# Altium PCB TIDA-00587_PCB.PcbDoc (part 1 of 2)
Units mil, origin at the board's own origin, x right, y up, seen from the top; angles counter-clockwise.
Board outline 4500 x 1700 mil, 4 copper layers (Top Layer, MidLayer1, MidLayer2, Bottom Layer), stack 61.6 mil thick; 120 components, 70 nets, 360 pads, 146 vias.
Unrouted connection lines stored in the file: 1.
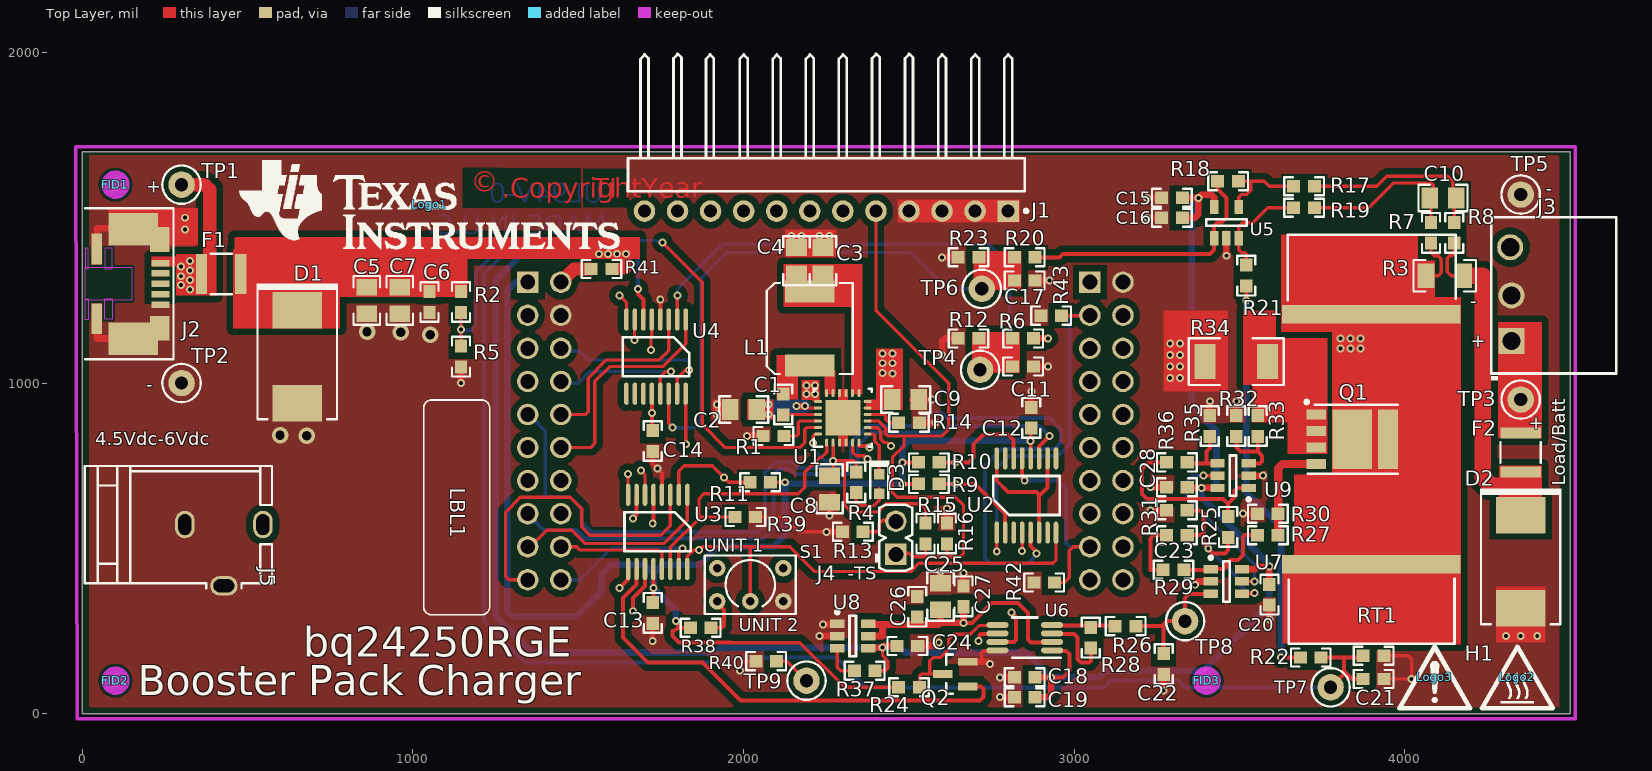
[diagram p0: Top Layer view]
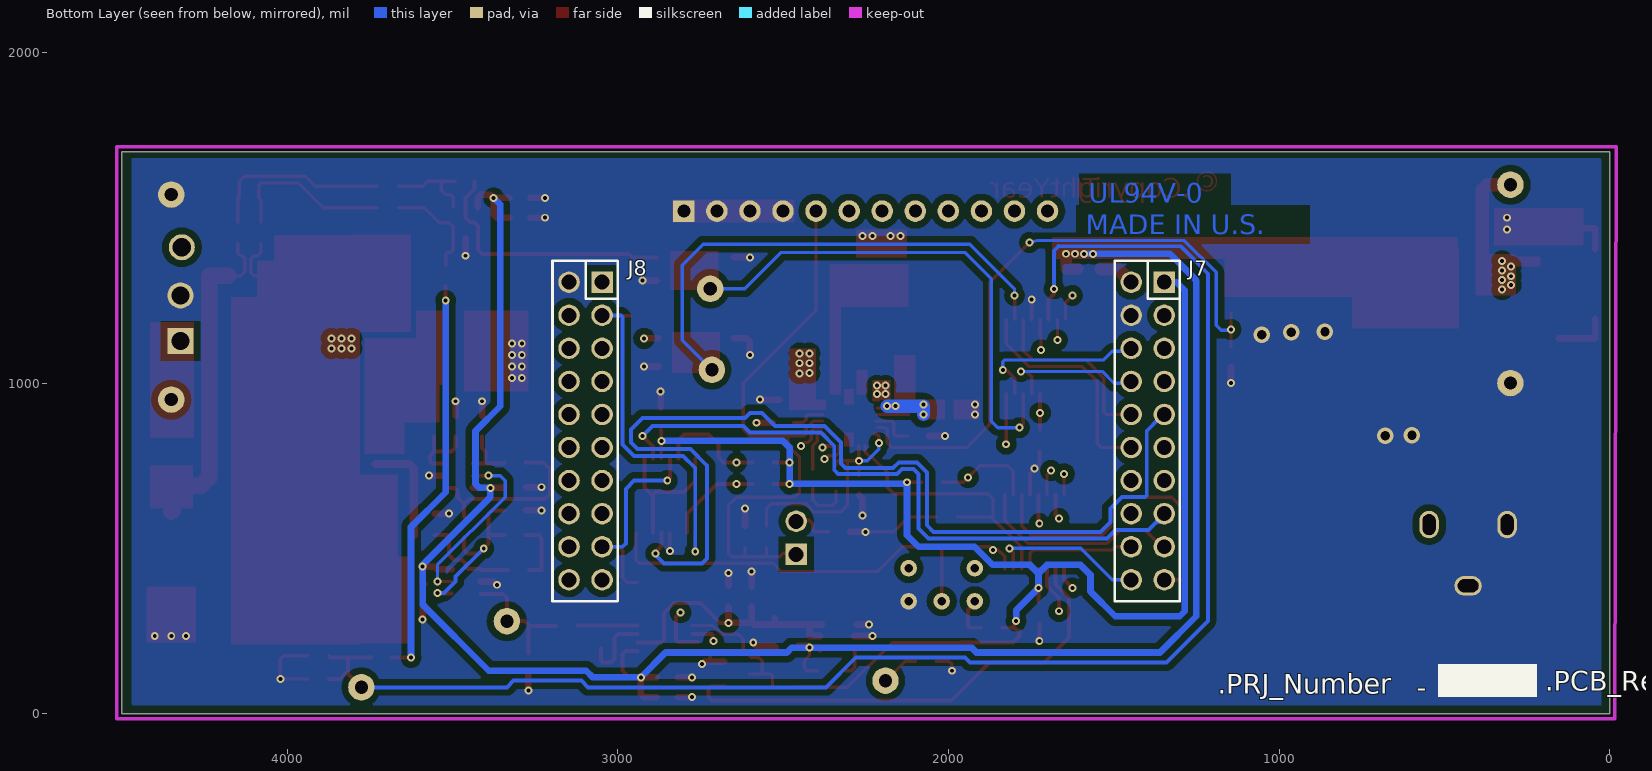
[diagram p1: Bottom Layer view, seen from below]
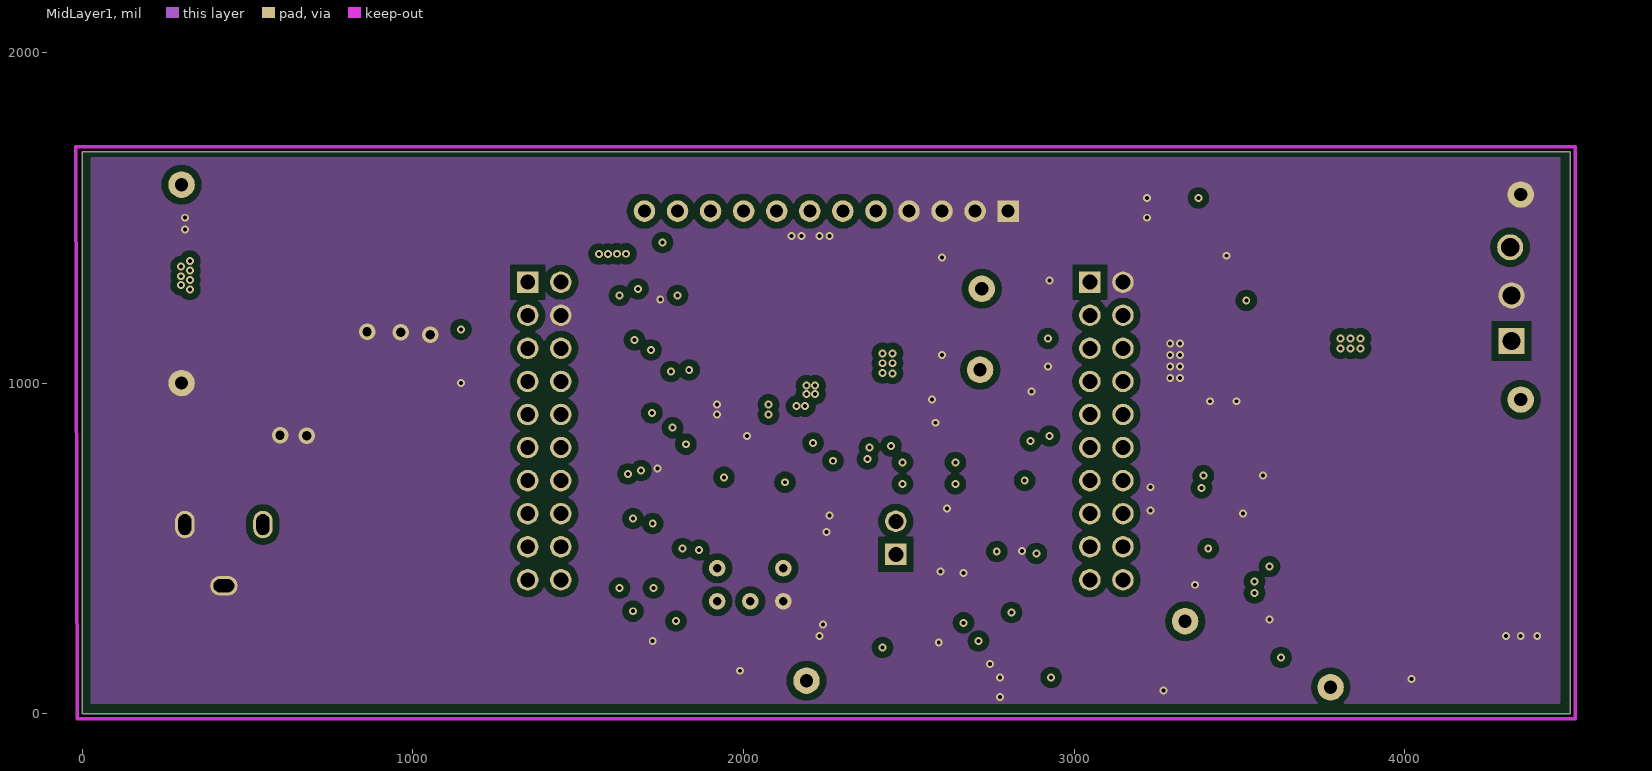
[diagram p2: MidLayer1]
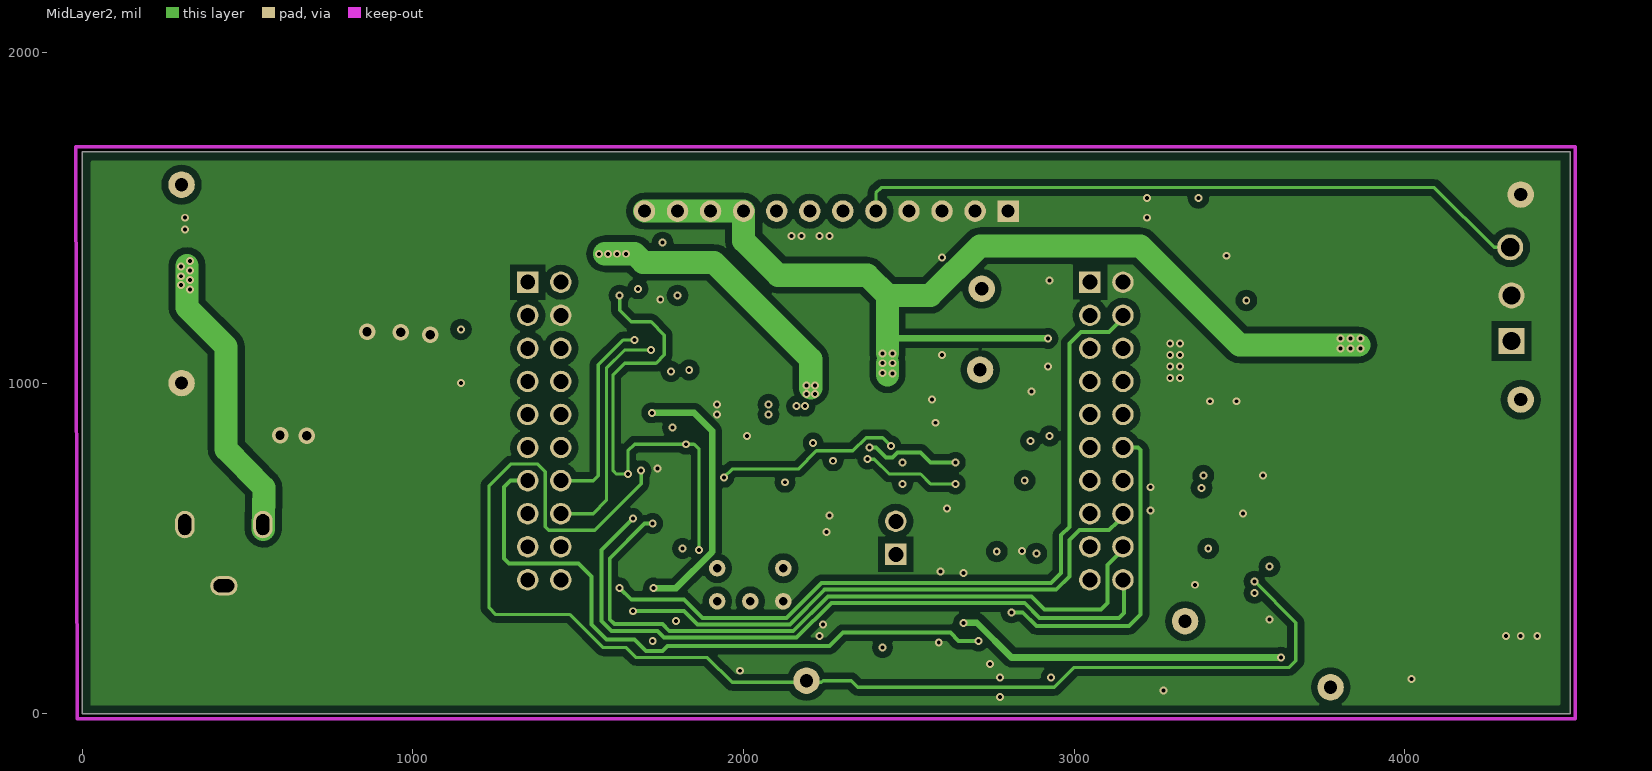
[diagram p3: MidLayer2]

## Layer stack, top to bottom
Top Solder: solder mask 0.4, Solder Resist, Dk 3.5
Top Layer: signal copper 1.4
Dielectric1: prepreg 8, FR-4, Dk 4.8
MidLayer1: signal copper 1.4
Dielectric2: core 40, FR-4, Dk 4.8
MidLayer2: signal copper 1.4
Dielectric3: prepreg 8, FR-4, Dk 4.8
Bottom Layer: signal copper 1.4
Bottom Solder: solder mask 0.4, Solder Resist, Dk 3.5

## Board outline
0,0 0,1700 4500,1700 4500,0 0,0

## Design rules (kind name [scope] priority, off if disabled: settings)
AcuteAngle [All] p1: minimum=4.50000000000000E+0001 checktracksonly=FALSE
AssemblyTestPointUsage [All] p1: valid=2
Clearance Clearance_BoardEdge_MountingHoles [OnCopper and InComponentClass('Mounting Holes') vs IsKeepOut] p1: gap=8
Clearance Clearance_BoardEdge_Poly [OnCopper and InPoly vs IsKeepOut] p2: gap=8
Clearance Clearance_BoardEdge [OnCopper and Not InComponentClass('Logo') and not InComponentClass('FiducialMark') and not InRegion(1000,500,4000,800) and Not IsKeepout vs IsKeepOut] p3: gap=8
Clearance Clearance_Poly [InPolygon] p4: gap=20
Clearance [All] p5: gap=4
ComponentClearance ComponentClearance_Shunt [InComponentClass('Header') vs InComponentClass('Shunt')] p1: gap=0 collisioncheckmode=3 verticalgap=0 showdistances=FALSE
ComponentClearance ComponentClearance_Logo [InComponentClass('Logo')] p2: gap=8 collisioncheckmode=3 verticalgap=8 showdistances=FALSE
ComponentClearance ComponentClearance_ScrewToNut [(HasFootprint('NY PMS 440 0025 PH')) vs (HasFootprint('Keystone_1902C'))] p3: gap=5 collisioncheckmode=3 verticalgap=10 showdistances=FALSE
ComponentClearance ComponentClearance_MountingHoles [InComponentClass('Mounting Holes')] p4: gap=12 collisioncheckmode=3 verticalgap=100000 showdistances=FALSE
ComponentClearance ComponentClearance_SmallPassives [HasFootprint('0201*') or HasFootprint('0402*') or HasFootprint('0508') or HasFootprint('0603*') or HasFootprint('0612') or HasFootprint('0805*') or HasFootprint('0815*') or HasFootprint('0830*') or HasFootprint('1206*') or HasFootprint('1210*') or HasFootprint('1808*') or HasFootprint('1812*') or HasFootprint('1825*') or HasFootprint('2010*') or HasFootprint('2220*') or HasFootprint('2225*') or HasFootprint('2512*') or HasFootprint('2728*') or HasFootprint('3518*') vs HasFootprint('0201*') or HasFootprint('0402*') or HasFootprint('0508') or HasFootprint('0603*') or HasFootprint('0612') or HasFootprint('0805*') or HasFootprint('0815*') or HasFootprint('0830*') or HasFootprint('1206*') or HasFootprint('1210*') or HasFootprint('1808*') or HasFootprint('1812*') or HasFootprint('1825*') or HasFootprint('2010*') or HasFootprint('2220*') or HasFootprint('2225*') or HasFootprint('2512*') or HasFootprint('2728*') or HasFootprint('3518*')] p5: gap=8 collisioncheckmode=3 verticalgap=8 showdistances=FALSE
ComponentClearance ComponentClearance_THtoSMT [IsThruComponent vs IsSMTComponent] p6: gap=8 collisioncheckmode=3 verticalgap=8 showdistances=FALSE
ComponentClearance ComponentClearance_THtoTH [IsThruComponent vs IsThruComponent] p7: gap=8 collisioncheckmode=3 verticalgap=8 showdistances=FALSE
ComponentClearance [All] p8: gap=8 collisioncheckmode=3 verticalgap=8 showdistances=FALSE
DiffPairsRouting [All] p1: maxlimit=100 minlimit=10 mostfreqgap=10 toplayer_minwidth=15 toplayer_maxwidth=15 toplayer_prefwidth=15 midlayer1_minwidth=15 midlayer1_maxwidth=15 midlayer1_prefwidth=15 midlayer2_minwidth=15 midlayer2_maxwidth=15 midlayer2_prefwidth=15 bottomlayer_minwidth=15 bottomlayer_maxwidth=15 bottomlayer_prefwidth=15 maxuncoupledlength=1000
FabricationTestPointUsage TestPointUsage [All] p1: valid=2 allowmultiple=FALSE
FabricationTestpoint Testpoint [All] p1: side=3 testpointundercomponent=TRUE minsize=40 maxsize=100 preferedsize=60 minholesize=0 maxholesize=40 preferedholesize=32 testpointgrid=1 allowsidetop=TRUE allowsidebottom=TRUE usegrid=TRUE gridtolerance=0.01
FanoutControl Fanout_LCC [IsLCC] p1: bgadir=Out bgaviamode=Centered fanoutstyle=Auto fanoutdirection=Alternating viagrid=1 // Fanout_LCC (Default Rule)
FanoutControl Fanout_BGA [IsBGA] p2: bgadir=Out bgaviamode=Centered fanoutstyle=Auto fanoutdirection=Alternating viagrid=1 // Fanout_BGA (Default Rule)
FanoutControl Fanout_Default [All] p4: bgadir=Out bgaviamode=Centered fanoutstyle=Auto fanoutdirection=Alternating viagrid=1 // Fanout_Default (Default Rule)
FanoutControl Fanout_Small [(CompPinCount < 5)] p5: bgadir=Out bgaviamode=Centered fanoutstyle=Auto fanoutdirection=OutThenIn viagrid=1 // Fanout_Small (Default Rule)
Height [All] p1: minheight=0 maxheight=500 prefheight=400
HoleSize [All] p1: absolutevalues=TRUE maxlimit=251 minlimit=3 maxpercent=80.000 minpercent=20.000
MinimumAnnularRing MinimumAnnularRing_ThermalPadVias [IsVia and InAnyComponent] p1: minimumring=3
MinimumAnnularRing [All] p2: minimumring=3
MinimumSolderMaskSliver MinimumSolderMaskSliver_Logo [InComponentClass('Logo') vs InComponentClass('Logo')] p1: minsoldermaskwidth=0.7
MinimumSolderMaskSliver [All] p2: minsoldermaskwidth=3.94
PlaneClearance [All] p1: clearance=10
PlaneConnect [All] p1: planeconnectstyle=Direct reliefexpansion=10 reliefentries=4 reliefconductorwidth=10 reliefairgap=10
PolygonConnect [All] p1: connectstyle=Direct reliefconductorwidth=10 reliefentries=4 polygonreliefangle="90 Angle" airgapwidth=10
RoutingVias ThermalPadVias [IsVia and InAnyComponent] p1: holewidth=7.87 width=19.68 viastyle="Through Hole" minholewidth=7.87 minwidth=19.68 maxholewidth=12.99 maxwidth=23.62
RoutingVias [All] p2: holewidth=16 width=34 viastyle="Through Hole" minholewidth=7.87 minwidth=26 maxholewidth=40 maxwidth=65
SMDToCorner [All] p1: distance=30000
SilkToSilkClearance [All] p1: silktosilkclearance=5
SilkToSolderMaskClearance SilkscreenOverComponentPads [IsPad] p1: minsilkscreentomaskgap=5 clearancetoexposedcopper=TRUE
SolderMaskExpansion [All] p1: expansion=1.97
UnpouredPolygon [All] p1: allowunpoured=FALSE
Width [All] p1: maxlimit=100 minlimit=6 preferedwidth=10 checkconnectedcopper=TRUE
13 further rules are at their usual default settings.

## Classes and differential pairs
component class Logo: Logo1
component class PR2182E3_Hdwr: FID1 FID2 FID3 LBL1 Logo1 Logo2 Logo3 ZZ1 ZZ2 ZZ3 ZZ4 ZZ5 ZZ6
component class FiducialMark: FID1 FID2 FID3
component class AssemblyNote: ZZ1 ZZ2 ZZ3 ZZ4 ZZ5 ZZ6
component class Label: LBL1
component class PR2182E3_Charger: C1 C2 C3 C4 C5 C6 C7 C8 C9 C10 C11 C12 C13 C14 C15 C16 C17 C18 C19 C20 C21 C22 C23 C24 C25 C26 C27 C28 D1 D2 D3 F1 F2 H1 J1 J2 J3 J4 J5 J7 J8 L1 Q1 Q2 R1 R2 R3 R4 R5 R6 R7 R8 R9 R10 R11 R12 R13 R14 R15 R16 R17 R18 R19 R20 R21 R22 R23 R24 R25 R26 R27 R28 R29 R30 R31 R32 R33 R34 R35 R36 R37 R38 R39 R40 R41 R42 R43 RT1 S1 TP1 TP2 TP3 TP4 TP5 TP6 TP7 TP8 TP9 U1 U2 U3 U4 U5 U6 U7 U8 U9
component class Header: J4

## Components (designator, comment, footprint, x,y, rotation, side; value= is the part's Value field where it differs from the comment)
C1 "GRM188R71H333KA61D" 0603 2120,935 r270 top
C2 "GRM21BR71E105KA99L" 0805_HV 2000,920 r0 top
C3 "GRM21BR61A106KE19L" 0805_HV 2240,1370 r90 top
C4 "GRM21BR61A106KE19L" 0805_HV 2160,1370 r90 top
C5 "GRM21BR61A106KE19L" 0805_HV 860,1250 r270 top
C6 "GRM21BR61A106KE19L" 0805_HV 960,1250 r270 top
C7 "C0603C104K3RACTU" 0603 1050,1245 r270 top
C8 "GRM21BR71E105KA99L" 0805_HV 2260,680 r90 top
C9 "GRM21BR71E105KA99L" 0805_HV 2490,950 r180 top
C10 "GRM21BR71E105KA99L" 0805_HV 4115,1560 r180 top
C11 "C0603C101J5GACTU" 0603 2845,1050 r0 top
C12 "C0603C104K3RACTU" 0603 2870,895 r90 top
C13 "C0603C104K3RACTU" 0603 1725,305 r270 top
C14 "C0603C104K3RACTU" 0603 1725,825 r270 top
C15 "C0603C104K3RACTU" 0603 3295,1560 r180 top
C16 "GRM1885C1H101JA01D" 0603 3295,1500 r180 top
C17 "C0603C101J5GACTU" 0603 2850,1310 r0 top
C18 "C0603C104K3RACTU" 0603 2850,110 r180 top
C19 "GRM1885C1H101JA01D" 0603 2850,50 r180 top
C20 "C0603C104K3RACTU" 0603 3590,360 r270 top
C21 "GRM188R71E104KA01D" 0603 3905,105 r0 top
C22 "C0603C101J5GACTU" 0603 3270,150 r270 top
C23 "GRM188R71E104KA01D" 0603 3310,540 r0 top
C24 "C0603C104K3RACTU" 0603 2495,205 r0 top
C25 "GRM21BR71E105KA99L" 0805_HV 2595,355 r270 top
C26 "C0603C104K3RACTU" 0603 2525,323.5 r90 top
C27 "GRM1885C1H101JA01D" 0603 2665,355 r90 top
C28 "C0603C104K3RACTU" 0603 3310,685 r180 top
D1 "1.5SMC6.8A" SMC 650,1080 r270 top
D2 "1.5SMC6.8A" SMC 4350,460 r270 top
D3 "LTST-C190CKT" LED_LTST-C190_Red 2410,695 r90 top
F1 "RF1824-000" FUSE_LR2 420,1330 r0 top
F2 "RF1824-000" FUSE_LR2 4350,790 r90 top
FID1 "Fiducial" Fiducial10-20 100,1600 r0 top
FID2 "Fiducial" Fiducial10-20 100,100 r0 top
FID3 "Fiducial" Fiducial10-20 3400,100 r0 top
H1 "DA-T268-101E" Ohmite_DA-T268-101E 3897.87,830 r90 top
J1 "PBC12SGBN" Sullins_PBC12SGBN 2250,1520 r180 top locked
J2 "UX60SA-MB-5ST" UX60SA-MB-5ST 140,1300 r270 top
J3 "OSTOQ031251" On-Shore_OSTOQ031251 4450,1265 r90 top
J4 "61300211121" WURTH_61300211121 2460,532 r90 top
J5 "PJ-102A" CONN_PJ-102A 428.11,572 r180 top
J7 "SSW-110-24-F-D" CONN_SSW-110-23-F-D 1347,1305 r90 bottom locked
J8 "SSW-110-24-F-D" CONN_SSW-110-23-F-D 3047,1305 r90 bottom
L1 "ELL-6RH1R0M" ELL6RH 2200,1165 r90 top
LBL1 "Size: 0.65\" x 0.20 \"" Label_650x200 1132,624 r270 top
Logo1 "Texas Instruments" TI_Stacked_Overlay_Medium 1050,1540 r0 top
Logo2 "CAUTION HOT SURFACE" IEC_HotSurface_Small 4340,110 r0 top
Logo3 "CAUTION.  READ USER GUIDE BEFORE USE" IEC_Caution_Small 4090,110 r0 top
Q1 "PSMN013-30YLC,115" LFPAK 3840,830 r270 top
Q2 "2N7002-7-F" SOT-23 2640,120 r180 top
R1 "CRCW0603133RFKEA" 0603 2090,840 r0 top
R2 "CRCW06031M00FKEA" 0603 1145,1245 r90 top
R3 "LVK12R010DER" 1206 4120,1324.45 r0 top
R4 "CRCW06031K50FKEA" 0603 2340,700 r270 top
R5 "CRCW0603365KFKEA" 0603 1145,1080 r90 top
R6 "CRCW06031M00FKEA" 0603 2845,1135 r0 top
R7 "CRCW060310R0FKEA" 0603 4078.7,1454.45 r270 top
R8 "CRCW060310R0FKEA" 0603 4148.7,1454.45 r270 top
R9 "CRCW06031K00FKEA" 0603 2560,695 r180 top
R10 "CRCW06031K00FKEA" 0603 2560,760 r180 top
R11 "CRCW060310K0FKEA" 0603 2050,700 r0 top
R12 "CRCW06031M00FKEA" 0603 2680,1135 r0 top
R13 "CRCW060310K0FKEA" 0603 2330,550 r0 top
R14 "CRCW0603124RFKEA" 0603 2500,880 r180 top
R15 "CRCW06034K99FKEA" 0603 2550,545 r90 top
R16 "CRCW06039K76FKEA" 0603 2615,545 r270 top
R17 "CRCW060310K0FKEA" 0603 3695,1595 r0 top
R18 "CRCW06031M00FKEA" 0603 3465,1610 r180 top
R19 "CRCW060310K0FKEA" 0603 3695,1530 r0 top
R20 "CRCW06031M00FKEA" 0603 2850,1380 r0 top
R21 "CRCW06031M00FKEA" 0603 3520,1325 r270 top
R22 "CRCW060310K0FKEA" 0603 3715,170 r180 top
R23 "CRCW06031M00FKEA" 0603 2680,1380 r0 top
R24 "CRCW06031M82FKEA" 0603 2500,80 r0 top
R25 "CRCW06031K00FKEA" 0603 3465,565 r270 top
R26 "CRCW06031K00FKEA" 0603 3155,265 r0 top
R27 "CRCW060310R0FKEA" 0603 3585,540 r0 top
R28 "CRCW060310K0FKEA" 0603 3050,230 r90 top
R29 "CRCW06034K75FKEA" 0603 3300,435 r0 top
R30 "CRCW060310K0FKEA" 0603 3585,605 r0 top
R31 "CRCW06031M00FKEA" 0603 3310,615 r180 top
R32 "CRCW060310K0FKEA" 0603 3490,870 r90 top
R33 "CRCW06031K00FKEA" 0603 3555,870 r90 top
R34 "CSRN2010FKR100" 2010M 3490,1065 r0 top
R35 "CRCW06031K00FKEA" 0603 3410,870 r90 top
R36 "CRCW060310K0FKEA" 0603 3310,760 r0 top
R37 "CRCW06031M00FKEA" 0603 2366,130 r0 top
R38 "CRCW060310K0FKEA" 0603 1870,260 r180 top
R39 "CRCW06031M00FKEA" 0603 2005,595 r180 top
R40 "CRCW06031M00FKEA" 0603 2068.19,159.13 r0 top
R41 "CRCW06030000Z0EA" 0603 1570,1345 r180 top
R42 "CRCW06032M00FKEA" 0603 2909,397 r0 top
R43 "CRCW06032M00FKEA" 0603 2930,1204 r0 top
RT1 "ERT-J1VG103FA" 0603 3905,175 r180 top
S1 "G12AP" SW_G1xAP 2020,390 r0 top
TP1 "5000" Keystone5000 300,1600 r0 top
TP2 "5001" Keystone5001 300,1000 r0 top
TP3 "5000" Keystone5000 4350,950 r0 top
TP4 "5002" Keystone5002 2715,1040 r0 top
TP5 "5001" Keystone5001 4350,1570 r0 top
TP6 "5002" Keystone5002 2720,1285 r0 top
TP7 "5002" Keystone5002 3775,80 r0 top
TP8 "5002" Keystone5002 3335,280 r0 top
TP9 "5002" Keystone5002 2190,100 r0 top
U1 "BQ24250RGER" RGE0024H_NV 2300,895 r90 top
U2 "TS3A44159PWR" PW0016A_N 2855,660 r90 top
U3 "TS3A44159PWR" PW0016A_N 1740,550 r270 top
U4 "TS3A44159PWR" PW0016A_N 1735,1080 r270 top
U5 "OPA333AIDBV" DBV0005A_N 3460,1485 r90 top
U6 "DAC8560IDDGK" DGK0008A_N 2850,230 r180 top
U7 "OPA334AIDBVR" DBV0006A_N 3460,400 r0 top
U8 "REF3225AIDBVR" DBV0006A_N 2330,235 r0 top
U9 "OPA334AIDBVR" DBV0006A_N 3480,720 r180 top
ZZ1 "This Assembly Note is for PCB labels only" AssemblyNoteLabel 327,7572 r0 top
ZZ2 "Mating Plug" AssemblyNote 327,7463.11 r0 top
ZZ3 "Transformer Wall Mnt 5V 2A" AssemblyNote 327,7374.56 r0 top
ZZ4 "CBL USB A-Mini B Con 3' 28/28 AWG" AssemblyNote 327,7286 r0 top
ZZ5 "J7, J8 Must be inserted from the bottom with the pins facing up. DO NOT CUT PINS." AssemblyNote 330,7195 r0 top
ZZ6 "Place a 200mil spot of Locktite Output 315 over RT1 and exposed area on the heatsink (You must use the recommended activator)" AssemblyNote 330,7110 r0 top

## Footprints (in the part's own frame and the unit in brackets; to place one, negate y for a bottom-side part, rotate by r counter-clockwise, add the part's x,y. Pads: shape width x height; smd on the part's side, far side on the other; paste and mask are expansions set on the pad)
0603 [mm] "0603 from SM-752 data"
  rect 1x0.95 smd: 1(-0.8,0) 2(0.8,0)
  silkscreen extent -1.52,-0.69 1.52,0.69, body extent -0.87,-0.47 0.87,0.47, height 0.85
0805_HV [mil] "0805 with 30mil clearance between pads"
  rect 50x63 smd: 1(-40,0) 2(40,0)
  silkscreen extent -74,-40 74,40, body extent -43,-29 43,29, height 43
1206 [mm] "1206 from SM-752 data"
  rect 1.3x1.85 smd: 1(-1.45,0) 2(1.45,0)
  silkscreen extent -2.4,-1.21 2.4,1.21, body extent -1.7,-0.9 1.7,0.9, height 1.35
2010M [mm]
  rect 1.6x2.7 smd: 1(-2.4,0) 2(2.4,0)
  silkscreen extent -3.65,-1.8 3.65,1.8, body extent -2.73,-1.45 2.73,1.45, height 1.66
AssemblyNote [mil] "Assembly Note"
AssemblyNoteLabel [mil] "Assembly Note for PCB Labels"
CONN_PJ-102A [mm] "CUI INC"
  oval 1.5x2.1 hole 1 slot 1.6 at 90 deg: 1(-3,0) 2(3,0)
  oval 2.1x1.5 hole 1 slot 1.6 at 0 deg: 3(0,4.7)
  silkscreen extent -3.7,-4.5 10.7,4.9, body extent -3.7,-4.5 10.7,4.9, height 11.02
CONN_SSW-110-23-F-D [mm] "SAMTEC"
  rect 1.65x1.65 hole 1.15: 1(0,0)
  round 1.65 hole 1.15: 2(0,2.54) 3(-2.54,0) 4(-2.54,2.54) 5(-5.08,0) 6(-5.08,2.54) 7(-7.62,0) 8(-7.62,2.54) 9(-10.16,0) 10(-10.16,2.54) 11(-12.7,0) 12(-12.7,2.54) 13(-15.24,0) 14(-15.24,2.54) 15(-17.78,0) 16(-17.78,2.54) 17(-20.32,0) 18(-20.32,2.54) 19(-22.86,0) 20(-22.86,2.54)
  silkscreen extent -24.51,-1.19 1.65,3.81, body extent -24.43,-1.24 1.57,3.81, height 8.59
DBV0005A_N [mm] "SOT23, 5-Leads, Body 2.9x1.6mm, Pitch 0.95mm, Lead Span 2.8mm, IPC Medium Density"
  rect 1.1x0.65 smd: 1(-1.2,0.95) 2(-1.2,0) 3(-1.2,-0.95) 4(1.2,-0.95) 5(1.2,0.95)
  silkscreen extent -0.25,-1.55 0.25,1.55, body extent -1.42,-1.46 1.42,1.46, height 1.08
DBV0006A_N [mm] "SOT23, 6-Leads, Body 2.9x1.6mm, Pitch 0.95mm, Lead Span 2.8mm, IPC Medium Density"
  rect 1.1x0.65 smd: 1(-1.2,0.95) 2(-1.2,0) 3(-1.2,-0.95) 4(1.2,-0.95) 5(1.2,0) 6(1.2,0.95)
  silkscreen extent -1.32,-1.55 0.25,1.95, body extent -1.42,-1.46 1.42,1.46, height 1.11
DGK0008A_N [mm] "TSOP, 8-Leads, Body 3x3mm, Pitch 0.65mm, IPC Medium Density"
  oval 1.7x0.45 smd: 1(-2.1,0.975) 2(-2.1,0.325) 3(-2.1,-0.325) 4(-2.1,-0.975) 5(2.1,-0.975) 6(2.1,-0.325) 7(2.1,0.325) 8(2.1,0.975)
  silkscreen extent -2.75,-1.55 0.95,1.55, body extent -2.45,-1.5 2.45,1.5, height 0.94
ELL6RH [mm] "Panasonic recommended land pattern"
  rect 1.7x3.8 smd: 1(-2.85,0) 2(2.85,0)
  silkscreen extent -3.5,-3.3 3.5,3.3, body extent -3.45,-3.25 3.45,3.25, height 2.8
Fiducial10-20 [mm]
  round 1 smd paste-0.5 mask+0.5: 1(0,0)
  Top Layer keep-out circle w1.178: c0,0 r0.5
FUSE_LR2 [mm] "TE Connectivity"
  rect 0.85x3.1 smd: 1(-1.5,0) 2(1.5,0)
  silkscreen extent -0.8,-1.55 0.8,1.55, body extent -1.71,-1.4 1.71,1.4, height 1
IEC_Caution_Small [mil]
  silkscreen extent -107,-93 107,92
IEC_HotSurface_Small [mil]
  silkscreen extent -107,-93 107,92
Keystone5000 [mil] "For Keystone 500x miniature loop terminals"
  round 80 hole 40: 1(0,0)
  silkscreen extent -58,-58 58,58, body extent -49,-49 49,49, height 182
Keystone5001 [mil] "For Keystone 500x miniature loop terminals"
  round 80 hole 40: 1(0,0)
  silkscreen extent -58,-58 58,58, body extent -49,-49 49,49, height 182
Keystone5002 [mil] "For Keystone 500x miniature loop terminals"
  round 80 hole 40: 1(0,0)
  silkscreen extent -58,-58 58,58, body extent -49,-49 49,49, height 182
Label_650x200 [mil] "Thermal Transfer Label"
  round 1 on Mech13: 0(0,0)
  silkscreen extent -325,-100 325,100, body extent -326,-101 326,101, height 1
LED_LTST-C190_Red [mm] "Lite-On"
  rect 0.8x0.8 smd: 1(-0.75,0) 2(0.75,0)
  silkscreen extent -1.1,-0.8 1.8,0.8, body extent -0.85,-0.45 0.85,0.45, height 0.9
LFPAK [mm] "Renesas LFPAK recommended land pattern  2008-05-26, page 17 of REJ11K0001_surface.pdf"
  rect 0.76x1.52 smd: 1(-1.905,-2.76) 2(-0.635,-2.76) 3(0.635,-2.76) 4(1.905,-2.76)
  rect 4.57x3.04 smd paste-1.52: 5(0,0)
  rect 4.57x1.52 smd paste-0.76: 6(0,2.76)
  silkscreen extent -2.99,-3.61 2.66,3.52, body extent -2.45,-3.23 2.45,3.2, height 1.18
Ohmite_DA-T268-101E [mm] "Ohmite"
  rect 1.4x13.7 smd: 1(-9.6,0) 2(9.6,0)
  silkscreen extent -15.7,-6.5 15.7,6.4, body extent -15.7,-6.4 15.69,6.32, height 10.16
On-Shore_OSTOQ031251 [mm] "TERM BLOCK 3x1, 3.5mm, TH"
  rect 2x2 hole 1.4: 1(-3.5,3.25)
  round 2 hole 1.4: 2(0,3.25) 3(3.7,3.35)
  silkscreen extent -6.5,-4.8 6,4.8, body extent -5.95,-4.75 5.95,4.75, height 7
PW0016A_N [mm] "TSOP, 16-Leads, Body 5x4.4mm, Pitch 0.65mm, IPC Medium Density"
  oval 1.7x0.35 smd: 1(-2.85,2.275) 2(-2.85,1.625) 3(-2.85,0.975) 4(-2.85,0.325) 5(-2.85,-0.325) 6(-2.85,-0.975) 7(-2.85,-1.625) 8(-2.85,-2.275) 9(2.85,-2.275) 10(2.85,-1.625) 11(2.85,-0.975) 12(2.85,-0.325) 13(2.85,0.325) 14(2.85,0.975) 15(2.85,1.625) 16(2.85,2.275)
  silkscreen extent -1.5,-2.55 1.5,2.55, body extent -3.21,-2.5 3.21,2.5, height 0.98
RGE0024H_NV [mm] "QFN, 24-Leads, Body 4x4mm, Pitch 0.5mm, Thermal Pad 2.7x2.7mm, TI Recommended"
  oval 0.6x0.24 smd: 1(-1.9,1.25) 2(-1.9,0.75) 3(-1.9,0.25) 4(-1.9,-0.25) 5(-1.9,-0.75) 6(-1.9,-1.25) 13(1.9,-1.25) 14(1.9,-0.75) 15(1.9,-0.25) 16(1.9,0.25) 17(1.9,0.75) 18(1.9,1.25)
  oval 0.24x0.6 smd: 7(-1.25,-1.9) 8(-0.75,-1.9) 9(-0.25,-1.9) 10(0.25,-1.9) 11(0.75,-1.9) 12(1.25,-1.9) 19(1.25,1.9) 20(0.75,1.9) 21(0.25,1.9) 22(-0.25,1.9) 23(-0.75,1.9) 24(-1.25,1.9)
  rect 2.7x2.7 smd paste-1.35: 25(0,0)
  silkscreen extent -2.22,-2.22 2.22,2.22, body extent -2.07,-2.07 2.07,2.07, height 1.01
SMC [mil] "Molded Diode, 2-Leads, Body 6.9x5.8mm, IPC Medium Density, based on OnSemi component dimensions and land patterns"
  rect 110x150 smd: 1(-140.49,0) 2(140.49,0)
  silkscreen extent -221,-124 189,123, body extent -156,-116 156,116, height 91
SOT-23 [mm] "SOT23, 3-Leads, Body 2.9x1.3mm, Pitch 0.95mm, Lead Span 2.5mm, IPC Medium Density"
  rect 1.5x0.6 smd: 1(-0.95,0.95) 2(-0.95,-0.95) 3(0.95,0)
  silkscreen extent 0.2,-1.5 0.7,1.5, body extent -1.16,-1.45 1.21,1.45, height 1
Sullins_PBC12SGBN [mm] "Sullins Right Angle Header"
  rect 1.65x1.65 hole 1: 1(-13.97,0)
  round 1.65 hole 1: 2(-11.43,0) 3(-8.89,0) 4(-6.35,0) 5(-3.81,0) 6(-1.27,0) 7(1.27,0) 8(3.81,0) 9(6.35,0) 10(8.89,0) 11(11.43,0) 12(13.97,0)
  silkscreen extent -15.47,-12.09 15.24,0.11, body extent -15.24,-12.14 15.24,0.32, height 3.56
SW_G1xAP [mil] "Switch, NKK G Series"
  round 50 hole 26: 1(-100,50) 3(100,50) 4(-100,-50) 5(0,-50) 6(100,-50)
  silkscreen extent -138,-88 138,89, body extent -138,-88 138,89, height 424
TI_Stacked_Overlay_Medium [mil]
  silkscreen extent -576,-136 576,134
UX60SA-MB-5ST [mm] "Hirose Connectors recommended land pattern"
  rect 0.5x1.4 smd: 1(-1.6,2.45) 2(-0.8,2.45) 3(0,2.45) 4(0.8,2.45) 5(1.6,2.45)
  rect 2.5x3.8 smd paste-1.25: 6(-4.2,0.35) 7(4.2,0.35)
  rect 1.9x1.5 smd paste-0.75: 6(-3.4,2.4) 7(3.4,2.4)
  rect 2.35x0.8 smd: 8(-2.675,-2.45) 9(2.675,-2.45)
  Top Layer keep-out region: -1.143,-1.267 -2.718,-1.267 -2.718,-1.826 -1.143,-1.826
  Top Layer keep-out region: -1.143,-3.096 -2.75,-3.1 -2.75,-3.35 -1.143,-3.35
  Top Layer keep-out region: -1.273,0.25 1.273,0.25 1.273,-1.55 1.273,-3.35 -1.273,-3.35 -1.27,-1.547
  Top Layer keep-out region: 1.143,-3.096 2.75,-3.1 2.75,-3.35 1.143,-3.35
  Top Layer keep-out region: 1.143,-1.242 2.718,-1.242 2.718,-1.826 1.143,-1.826
  silkscreen extent -5.8,-3.35 5.8,3.45, body extent -4.95,-4.2 4.95,2.94, height 4.38
WURTH_61300211121 [mm] "Header, 2.54mm, 2x1, TH"
  rect 1.65x1.65 hole 1.15: 1(-1.27,0)
  round 1.65 hole 1.15: 2(1.27,0)
  silkscreen extent -2.54,-1.27 2.54,1.6, body extent -2.54,-1.27 2.54,1.27, height 8.54

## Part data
C1: "CAP, CERM, 0.033uF, 50V, +/-10%, X7R, 0603"
C2 C8 C9 C10 C25: "CAP, CERM, 1uF, 25V, +/-10%, X7R, 0805"
C3 C4 C5 C6: "CAP, CERM, 10uF, 10V, +/-10%, X5R, 0805"
C7 C12 C13 C14 C15 C18 C20 C21 C23 C24 C26 C28: "CAP, CERM, 0.1uF, 25V, +/-10%, X7R, 0603"
C11 C16 C17 C19 C22 C27: "CAP, CERM, 100pF, 50V, +/-5%, C0G/NP0, 0603"
D1 D2: "Diode, TVS, Uni, 6.8V, 1500W, SMC"
D3: "LED, Red, SMD"
F1 F2: "Fuse, Resettable, 1.9A, 6V, SMD"
FID1 FID2 FID3: "Fiducial mark.  There is nothing to buy or mount."
H1: "Heatsink, TO-268 [D3]SMT"
J1: "Header, 12x1, 100mil, R/A, TH"
J2: "Connector, Receptacle, Mini-USB Type B, R/A, Top Mount SMT"
J3: "Header, 3x1 3.5mm, TH"
J4: "Header, 2.54 mm, 2x1, Gold, TH"
J5: "Connector, DC Jack 2.1X5.5 mm, TH"
J7 J8: library part SSW-110-23-F-D, "Connector, Receptacle, 100mil, 10x2, Gold plated, TH"
L1: "Inductor, Shielded Drum Core, Ferrite, 1uH, 3A, 0.019 ohm, SMD"
LBL1: library part THT-14-423-10, "Thermal Transfer Printable Labels, 0.650\" W x 0.200\" H - 10,000 per roll"
Logo1: library part TI_Logo, "Texas Instrument Corporate Signature"
Logo2: library part IEC_HotSurface, "IEC 61010-1 Hot Surface Warning"
Logo3: library part IEC_Caution, "IEC 61010-1 Caution Warning"
Q1: "MOSFET, N-CH, 30V, 32A, LFPAK"
Q2: "MOSFET, N-CH, 60V, 0.17A, SOT-23"
R1: "RES, 133 ohm, 1%, 0.1W, 0603"
R2 R6 R12 R18 R20 R21 R23 R31 R37 R39 R40: "RES, 1.00Meg ohm, 1%, 0.1W, 0603"
R3: "RES, 0.01 ohm, 0.5%, 0.5W, 1206"
R4: "RES, 1.50k ohm, 1%, 0.1W, 0603"
R5: "RES, 365k ohm, 1%, 0.1W, 0603"
R7 R8 R27: "RES, 10.0 ohm, 1%, 0.1W, 0603"
R9 R10 R25 R26 R33 R35: "RES, 1.00k ohm, 1%, 0.1W, 0603"
R11 R13 R17 R19 R22 R28 R30 R32 R36 R38: "RES, 10.0k ohm, 1%, 0.1W, 0603"
R14: "RES, 124 ohm, 1%, 0.1W, 0603"
R15: "RES, 4.99k ohm, 1%, 0.1W, 0603"
R16: "RES, 9.76k ohm, 1%, 0.1W, 0603"
R24: "RES, 1.82Meg ohm, 1%, 0.1W, 0603"
R29: "RES, 4.75k ohm, 1%, 0.1W, 0603"
R34: "RES, 0.1 ohm, 1%, 1W, 2010"
R41: "RES, 0, 5%, 0.1 W, 0603"
R42 R43: "RES, 2.00Meg ohm, 1%, 0.1W, 0603"
RT1: "Thermistor NTC, 10.0k ohm, 1%, 0603"
S1: "Switch, Toggle, SPDT 1Pos, TH"
TP1 TP3: "Test Point, Miniature, Red, TH"
TP2 TP5: "Test Point, Miniature, Black, TH"
TP4 TP6 TP7 TP8 TP9: "Test Point, Miniature, White, TH"
U1: "2A Single Input I2C, Standalone Switch-Mode Li-Ion Battery Charger with Power-Path Management, RGE0024H"
U2 U3 U4: "0.45 ohm QUAD SPDT ANALOG SWITCH QUAD-CHANNEL 2:1 MULTIPLEXER/DEMULTIPLEXER WITH TWO CONTROLS, PW0016A"
U5: "1.8-V, microPower, CMOS Operational Amplifiers, Zero-Drift Series, DBV0005A"
U6: "16-Bit, Ultra-Low Glitch, Voltage Output Digital-to-Analog Converter with 2.5V, 2ppm/°C Internal Reference, DGK0008A"
U7 U9: "0.05 uV/C Max, Single-Supply CMOS Operational Amplifier, 2.7 to 5.5 V, -40 to 125 degC, 6-pin SOT23 (DBV0006A), Green (RoHS & no Sb/Br)"
U8: "2.5 V, 4 ppm / degC, 100 uA Series (Bandgap) Voltage Reference, -40 to 125 degC, 6-pin SOT-23 (DBV), Green (RoHS & no Sb/Br)"
ZZ1: library part AssemblyNoteLabel
ZZ2: library part AssemblyNote, "This is the mating Plug for Connector J3"
ZZ3 ZZ4 ZZ5 ZZ6: library part AssemblyNote

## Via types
v1: diameter 24, hole 12, Top Layer to Bottom Layer, 141 vias
v2: diameter 50, hole 28, Top Layer to Bottom Layer, 4 vias
v3: diameter 50, hole 28, Top Layer to Bottom Layer, tented bottom, 1 vias

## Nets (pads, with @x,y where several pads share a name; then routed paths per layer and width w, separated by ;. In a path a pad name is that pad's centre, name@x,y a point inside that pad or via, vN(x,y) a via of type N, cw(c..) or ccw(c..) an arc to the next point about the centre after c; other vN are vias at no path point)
3.3VDC: C12.1 C13.1 C14.1 J7.1 R9.2 R10.2 R11.2 R24.1 R38.2 U2.12 U3.12 U4.12 | length 5291.8
  Top Layer w10: 1960,215 2170,215 2305,80 R24.1@2468.5,80 ; U2.12@2867.8,772.2 v1(2867.8,825) 2867.8,856.3 C12.1@2870,858.5
  Top Layer w12: C14.1@1722.2,859.29 v1(1722.2,910) U4.12@1722.2,967.8 ; C13.1@1727.2,338.7 v1(1727.2,380) U3.12@1727.2,437.8 ; v1(1795,280) 1805,260 ; R38.2@1838.5,260 1805,260 ; 1960,215 1805,215 1785,235 1785,250 1805,260 ; R11.2@2081.5,700 v1(2125,700) ; v1(2480,695) R9.2@2528.5,695 ; v1(2480,760) R10.2@2528.5,760
  MidLayer2 w20: v1(1722.2,910) 1850,910 1905,855 1905,489.41 1795.59,380 v1(1727.2,380)
  Bottom Layer w10: v1(2125,700) v1@2130,695
  Bottom Layer w20: J7.1@1330,1300 1325,1305 1310,1305 1285,1280 1285,310 1300,295 1495,295 1570,370 1570,420 1600,450 1701.61,450 1727.2,424.41 ; v1(1795,280) 1795,312.2 v1(1727.2,380) 1727.2,424.41 ; v1(2125,700) 2125,540 2090,505 1920.59,505 1865.59,450 1752.8,450 1727.2,424.41 ; v1@2130,695 v1(2480,695) v1(2480,760) 2480,805 2500,825 v1(2867.8,825)
5VDC: C5.1 C6.1 C7.1 C15.1 C16.1 C18.1 C19.1 C20.1 C24.1 C28.1 D1.1 F1.2 R2.2 R37.2 R41.1 U1.19 U5.5 U6.1 U7.6 U8.4 U9.6 | length 7262.5
  Top Layer w10: v1@2190,965 v1(2190,967) 2190,970 2210.79,949.21 2225.2,949.21 ; R37.2@2396.5,130 2428.16,130 2436.18,138.02 2436.18,158.82 2420,175 v1(2420,200)
  Top Layer w12: v1(2930,110) 2965,110 2985,130 2985,180 2975,190 U6.1@2940.2,190
  Top Layer w20: U8.4@2387,195 2392,200 v1(2420,200) 2425,205 2453.5,205 C24.1@2458.5,200 ; C19.1@2881.5,50 2920,50 2930,60 v1(2930,110) C18.1@2881.5,110 ; C16.1@3326.5,1500 3365,1500 3375,1510 v1(3375,1560) ; C15.1@3326.5,1560 v1(3375,1560) ; C28.1@3343.5,683 v1(3385,683) U9.6@3438,683 ; U5.5@3422.6,1532.24 3422.6,1561.14 3413.74,1570 3385,1570 v1(3375,1560) ; U7.6@3502,437 3547,437 3555,445 v1(3590,445) 3590,396.5 C20.1@3585,391.5
  Top Layer w35: R41.1@1608.22,1346 1644,1346 v1(1644,1391)
  MidLayer2 w10: v1@1616,1390 v1(1617,1391)
  MidLayer2 w70: v1@1580,1391 v1@1626,1391 ; v1(1617,1391) v1(1644,1391) 1670,1391 1696,1365 1910,1365 2203,1072 2203,985.31
  Bottom Layer w20: v1@1590,1391 1330,1391 1250,1310 1250,295 1360,185 1915,185 1930,200 v1(2420,200) 2473.35,200 2488.35,185 2855,185 v1(2930,110) 3075,110 3095,130 3390,130 3590,330 v1(3590,445) 3590,450 3385,655 v1(3385,683) 3418,683 3430,695 3430,855 3355.21,929.79 3355.21,1540.21 v1(3375,1560)
  other v1: 2216,967 2190,992 2216,992 1562,1390 1590,1390
ADC_1: J7.6 U4.15 | length 523
  Top Layer w10: U4.15@1798.98,967.8 1798.98,1013.98 1825,1040 v1(1835.39,1040)
  Bottom Layer w10: J7.6@1450,1080 1466,1096 1504,1096 1530,1070 1830,1070 1835.39,1064.61 v1(1835.39,1040)
ADC_2: J7.8 U4.13 | length 442.7
  Top Layer w10: U4.13@1747.8,967.8 1747.8,1018.74 1764.06,1035 v1(1780,1035)
  Bottom Layer w10: J7.8@1450,980 1469,999 1499,999 1535,1035 v1(1780,1035)
ADC_3: J7.10 U4.3 | length 567.4
  Top Layer w10: J7.10@1450,880 1475,905 1522,905 1530,913 1530,1015 1585,1070 1745,1070 1773.39,1098.39 U4.3@1773.39,1192.2
ADC_4: J7.12 U4.1 | length 697.4
  Top Layer w10: J7.12@1450,780 1475,805 1537,805 1550,818 1550,1005 1595,1050 1755,1050 1824.57,1119.57 U4.1@1824.57,1192.2
ADC_5: J7.14 U4.7 | length 665.3
  Top Layer w10: v1(1670,1130) 1670,1191.18 U4.7@1671.02,1192.2
  MidLayer2 w10: J7.14@1450,680 1475,705 1545,705 1560,720 1560,1055 1635,1130 v1(1670,1130)
ADC_6: J7.16 U4.5 | length 812.8
  Top Layer w10: v1(1720,1100) 1720,1140 1722.2,1142.2 U4.5@1722.2,1192.2
  MidLayer2 w10: J7.16@1450,580 1475,605 1545,605 1585,645 1585,1045 1640,1100 v1(1720,1100)
ADC_CH_IDC: C17.1 R20.1 R23.2 TP6.1 U4.14 | length 1559.6
  Top Layer w10: U4.14@1773.39,967.8 1773.39,876.61 v1(1785,865)
  Bottom Layer w10: v1(1785,865) 1850,865 1870,885 1870,1315 1950,1395 2505,1395 2615,1285 TP6.1@2720,1285
ADC_CH_VDC: C11.1 R6.1 R12.2 TP4.1 U4.2 | length 1534.2
  Top Layer w10: U4.2@1798.98,1192.2 1798.98,1263.98 v1(1800,1265)
  Bottom Layer w10: v1(1800,1265) 1800,1285 1935,1420 2741.46,1420 2805,1356.46 2805,1130 TP4.1@2715,1040
ADC_HS_TEMP: C21.1 R22.1 RT1.2 TP7.1 U4.6 | length 4747.7
  Top Layer w12: v1(1680,1285) 1680,1270 1696.61,1253.39 U4.6@1696.61,1192.2 ; R22.1@3746.5,170 3815,170 ; TP7.1@3775,80 3815,120 3815,130 ; C21.1@3873.5,105 3840,105 3815,130 ; RT1.2@3873.5,175 3868.5,170 3815,170 ; 3815,130 3815,170
  Bottom Layer w12: v1(1680,1285) 1680.06,1400 1666.82,1413.82 1296.5,1413.5 1214.5,1330.5 1215,280 1340,155 1935,155 1950,170 2280,170 2370,80 3090,80 3110,100 3315,100 3335,80 TP7.1@3775,80
CE_1: J7.20 U3.15 | length 481.5
  Top Layer w10: U3.15@1803.98,437.8 1803.98,488.98 v1(1815,500)
  Bottom Layer w10: J7.20@1450,380 1475,405 1505,405 1600,500 v1(1815,500)
CE_2: J7.18 U3.13 | length 369.9
  Top Layer w10: J7.18@1450,480 1475,505 1495,505 1505,495 1745,495 1752.8,487.2 U3.13@1752.8,437.8
CHG/LOAD: C9.2 H1.1 H1.2 J1.9 J1.10 J1.11 J1.12 Q1.5 Q1.6 R3.1 R6.2 R7.2 U1.11 U1.12 | length 3482.6
  Top Layer w10: C9.2@2450.47,950 v1(2450.47,1029.53) ; R3.1@4062.91,1324.45 4100.31,1324.45 4110,1334.13 4110,1375 4100,1385 4088.2,1385 4078.7,1394.5 R7.2@4078.7,1422.95
  Top Layer w20: R6.2@2876.5,1135 v1(2920,1135)
  MidLayer2 w20: 2435,1135 v1(2920,1135)
  MidLayer2 w70: J1.12@1700,1520 J1.11@1800,1520 J1.10@1900,1520 J1.9@2000,1520 2000,1430 2104,1326 2374,1326 2435,1265 ; 2435,1025 2435,1060 ; 2435,1090 2435,1135 2435,1265 ; v1@3860,1115 3500,1115 3200,1415 2715,1415 2565,1265 2435,1265
  other v1: 2420,1030 2420,1060 2450,1060 2420,1090 2450,1090 3805,1105 3835,1105 3865,1105 3805,1135 3835,1135 3865,1135
CS_1: J7.15 U2.11 | length 1981.8
  Top Layer w12: U2.11@2893.39,772.2 2893.39,808.39 v1(2925,840)
  Bottom Layer w12: J7.15@1350,580 1370,580 1395,555 1495,555 1520,530 2060,530 2090,560 2090,725 2105,740 2140,740 2155,725 2333.35,725 2345,736.65 2345,809.9 2385.1,850 2600,850 2620,870 2895,870 v1(2925,840)
CS_2: J7.9 U2.5 | length 3034.6
  Top Layer w12: U2.5@2867.8,547.8 2867.8,506.69 2885,489.49 v1(2885,485)
  Bottom Layer w12: J7.9@1350,880 1362.5,892.5 1400,855 1400,660 1405,655 1475,655 1510,620 1510,580 1540,550 2045,550 2065,570 2065,730 2095,760 2150,760 2167,743 2310.8,743 2325,757.2 2325,820 2375,870 2524,870 2564,910 2600,910 2615,895 2925,895 2960,860 2960,820 2940,800 2780,800 2730,750 2730,470 2745,455 2860,455 2885,480 v1(2885,485)
EL_EN: R40.2 TP9.1 U3.6 U7.5 U9.5 | length 4728.1
  Top Layer w10: v1(1690,735) 1701.61,723.39 U3.6@1701.61,662.2 ; R40.2@2099.68,159.13 2130.87,159.13 TP9.1@2190,100 ; v1(3390,720) U9.5@3438,720 ; U7.5@3502,400 v1@3539.5,400
  MidLayer2 w10: v1(1690,735) 1690,695 1550,555 1410,555 1400,565 1400,732 1377,755 1295,755 1230,690 1230,320 1250,300 1475,300 1575,200 1645,200 1675,170 1890,170 1965,95 2235,95 2240,100 2325,100 2345,80 2940,80 3000,140 3650,140 3670,160 3670,275 v1(3545,400)
  Bottom Layer w10: v1(3390,720) 3355,720 3340,705 3340,655 3545,450 v1(3545,400)
EL_EN_1: J8.20 U3.7 | length 2170.2
  Top Layer w12: v1(1665,590) 1676.02,601.02 U3.7@1676.02,662.2
  MidLayer2 w12: v1(1665,590) 1570,495 1570,280 1600,250 1738.98,250 1758.98,230 2160,230 2265,335 2850,335 2895,290 3135,290 3150,305 J8.20@3150,380
EL_EN_2: J8.18 U3.5 | length 2211.9
  Top Layer w12: v1(1725,575) 1727.2,577.2 U3.5@1727.2,662.2
  MidLayer2 w12: v1(1725,575) 1700,575 1595,470 1595,285 1609,271 1754,271 1775,250 2149.94,250 2254.94,355 2870,355 2910,315 3080,315 3100,335 3100,450 3130,480 J8.18@3150,480
GND: C2.1 C3.2 C4.2 C5.2 C6.2 C7.2 C8.1 C9.1 C11.2 C12.2 C13.2 C14.2 C15.2 C16.2 C17.2 C18.2 C19.2 C20.2 C21.2 C22.2 C24.2 C25.1 C26.2 C27.2 C28.2 D1.2 D2.2 J1.1 J1.2 J1.3 J1.4 J2.5 J2.6 J2.7 J2.8 J2.9 J3.2 J5.2 J5.3 J7.4 J8.2 Q2.2 R1.1 R5.1 R12.1 R13.1 R14.1 R16.1 R23.1 R30.1 R31.2 R32.2 R34.1 R35.2 R39.1 R40.1 R42.1 R43.1 RT1.1 S1.6 TP2.1 TP5.1 U1.3 U1.4 U1.15 U1.16 U1.25 U2.4 U3.4 U4.4 U5.2 U6.8 U7.2 U8.1 U8.2 U9.2 | length 3500.6
  Top Layer w10: v1(1989,130) 1990,131 1990,151 1998.13,159.13 R40.1@2036.69,159.13 ; R39.1@2036.5,595 2120,595 2165,550 v1(2250,550) ; v1(2842.2,492.2) U2.4@2842.2,547.8 ; C21.2@3936.5,105 v1(4020,105) 4020,165 4010,175 RT1.1@3936.5,175
  Top Layer w12: v1(1725,220) C13.2@1725,273.5 ; C14.2@1725,793.5 1725,755 1752.8,727.2 U3.4@1752.8,662.2 ; U4.4@1747.8,1192.2 v1(1747.8,1252.8) ; 2715.2,157.4 2720,162.2 2720,185 2725,190 U6.8@2756.6,190
  Top Layer w20: J2.9@43.54,1194.68 43.54,1136.46 45.35,1134.65 J2.7@153.78,1134.65 ; J2.8@43.54,1405.31 43.54,1468.54 150.59,1468.54 J2.6@153.78,1465.35 ; v1(1145,1000) R5.1@1145,1048.5 ; 1925,920 C2.1@1960,920 C2.1@1970.47,920 ; v1(2010,840) R1.1@2058.5,840 ; v1(2229,235) 2277.5,235 U8.2@2286,235 ; v1(2240,270) U8.1@2277.5,270 ; v1(2250,550) R13.1@2298.5,550 ; v1(2260,600) C8.1@2260,640 2260,650.94 C8.1@2270,660.94 ; C9.1@2509.53,950 C9.1@2530,950 v1(2570,950) ; C24.2@2521.5,200 C24.2@2526.5,205 2580,205 v1(2590,215) ; R14.1@2531.5,880 v1(2580,880) ; C25.1@2595,384.53 C25.1@2595,395 v1(2595,430) ; v1(2600,1085) 2600,1125 2610,1135 R12.1@2648.5,1135 ; v1(2600,1380) R23.1@2648.5,1380 ; R16.1@2615,566.5 R16.1@2615,576.5 v1(2615,620) ; C27.2@2665,386.5 v1(2665,425) ; Q2.2@2677.4,157.4 2715.2,157.4 v1@2737.6,157.4 ; v1(2775,50) C19.2@2818.5,50 ; v1(2775,110) C18.2@2818.5,110 ; C12.2@2870,926.5 v1(2870,975) v1@2870,980 ; C11.2@2876.5,1050 v1(2920,1050) ; C17.2@2881.5,1310 v1(2925,1310) ; v1(3220,1500) C16.2@3263.5,1500 ; v1(3220,1560) C15.2@3263.5,1560 ; v1(3230,615) R31.2@3278.5,615 ; v1(3230,685) C28.2@3278.5,685 ; v1(3270,70) C22.2@3270,118.5 ; v1(3320,1085) 3391.02,1085 3395.51,1089.49 R34.1@3395.51,1065 3395.51,1045.51 R34.1@3376.02,1045.51 ; v1@3325,1050 3380.51,1050 R34.1@3376.02,1045.51 ; v1(3365,390) 3375,400 U7.2@3415,400 ; R34.1@3375.51,1045 R34.1@3376.02,1045.51 ; R35.2@3410,901.5 v1(3410,945) ; v1(3460,1385) U5.2@3460,1437.76 ; R32.2@3490,901.5 v1(3490,945) ; v1(3510,605) R30.1@3553.5,605 ; U9.2@3525,720 v1(3570,720) ; C20.2@3585,328.5 3590,323.5 v1(3590,285) ; v1@4305.49,235.49 4305.49,329.51 D2.2@4350,329.51 ; v1(4350,235) D2.2@4350,319.51 D2.2@4350,329.51 ; v1@4399.51,235.49 4399.51,329.51 D2.2@4350,329.51
  other v1: 2745,150 4305,235 4400,235 1738.9,741.1 1920,905 1920,935 3290,1015 3320,1015 3290,1050 3320,1050 3290,1085 3290,1120 3320,1120 2145,1445 2175,1445 2230,1445 2260,1445 310,1465 310,1500
  other v2: 679,841 598,842 1052,1146 963,1154
  other v3: 861,1155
